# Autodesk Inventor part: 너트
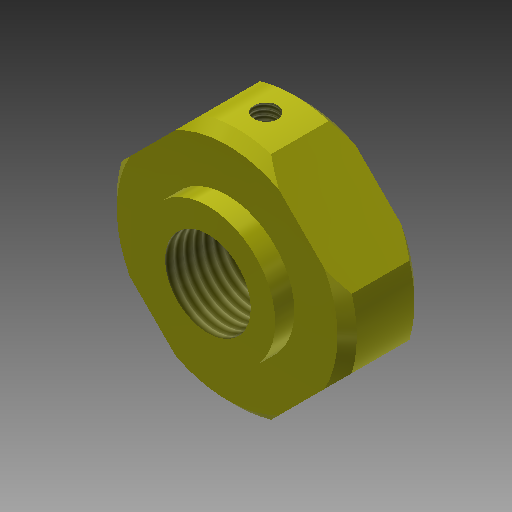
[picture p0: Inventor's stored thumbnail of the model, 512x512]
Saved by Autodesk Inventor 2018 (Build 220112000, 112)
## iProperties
Created: 2020-03
Part Number: 너트
Material: 스테인리스강
Document SubType Name: Modeling
Designer: mduedu
Density: 8.08 g/cm^3
Appearance: 노란색
Mass: 25.4806 g
Surface Area: 17.4692 cm^2
Volume: 3.15354 cm^3
Author: mduedu
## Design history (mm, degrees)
sketch "스케치1"
  geometry: C1 r 12.5 at (0, 0); 1 further point
  constraints: 1 centre point, 1 coincident
  dimensions: "d0" = 25 diameter of C1
extrude "돌출1" new body sketch "스케치1" distance "d1" = 8; taper "d2" = 0 deg
chamfer "모따기1" distance "d3" = 1; stored, may be unused: second distance "d4" = 2, angle "d5" = 45 deg
sketch "스케치2"
  geometry: L1 (-15.556, 0)-(0, 15.556); L2 (0, 15.556)-(15.556, 0); L3 (15.556, 0)-(0, -15.556); L4 (0, -15.556)-(-15.556, 0); L5 (-15.556, 0)-(15.556, 0); L6 (0, 15.556)-(0, -15.556); C1 r 12.5 at (0, 0) reference; 1 further point
  constraints: 12 end point, 2 midpoint, 2 parallel, 1 horizontal, 1 perpendicular, 1 vertical
  dimensions: "d8" = 22 distance of L1.end L2.end
extrude "돌출2" sketch "스케치2" stored distance "d10" = 8; taper "d11" = 0 deg
sketch "스케치3"
  geometry: C1 r 7 at (0, 0); 1 further point
  constraints: 1 centre point, 1 coincident
  dimensions: "d12" = 14 diameter of C1
extrude "돌출3" join sketch "스케치3" distance "d13" = 2; taper "d14" = 0 deg
hole "구멍1" diameter "d17" = 8.917; stored, may be unused: countersink angle "d21" = 90 deg, drill point angle "d23" = 118 deg; dims "d15" = 10, "d16" = 10, "d18" = 6, "d19" = 4, "d20" = 2, "d22" = 8
sketch "스케치4"
  geometry: 2 further points
  constraints: 1 vertical alignment
  dimensions: "d24" = 4 distance of point (0, 4) point (0, 0)
hole "구멍2" sketch "스케치4" at (0, 4) diameter "d25" = 2.459; stored, may be unused: countersink angle "d29" = 90 deg, drill point angle "d31" = 118 deg; dims "d26" = 6, "d27" = 4, "d28" = 2, "d30" = 8
node "솔리드1"
